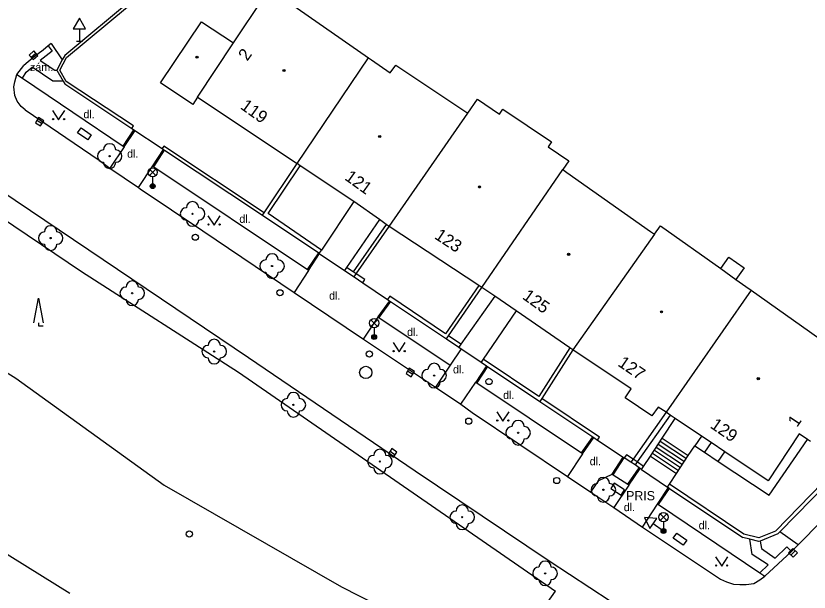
# Model space of a CAD drawing. Extents: x -598341 to -594502, y -1162301 to -1161406.
# Drawn here: x -594705.4 to -594641, y -1161528.7 to -1161481.9 of the extents above; entities that cross this region are included whole.
import ezdxf

# ---------------------------------------------------------------- set-up
doc = ezdxf.new("R2010")
doc.units = 0
for name, color, linetype in [('Vrstva 10', 7, 'Continuous'), ('Vrstva 11', 7, 'Continuous'), ('Vrstva 22', 7, 'Continuous'), ('Vrstva 24', 7, 'Continuous'), ('Vrstva 27', 7, 'Continuous'), ('Vrstva 28', 7, 'Continuous'), ('Vrstva 33', 7, 'Continuous'), ('Vrstva 34', 7, 'Continuous'), ('Vrstva 36', 7, 'Continuous'), ('Vrstva 39', 7, 'Continuous'), ('Vrstva 40', 7, 'Continuous'), ('Vrstva 41', 7, 'Continuous'), ('Vrstva 46', 7, 'Continuous'), ('Vrstva 5', 7, 'Continuous'), ('Vrstva 7', 7, 'Continuous'), ('Vrstva 8', 7, 'Continuous')]:
    doc.layers.add(name, color=color, linetype=linetype)

msp = doc.modelspace()

# ---------------------------------------------------------------- linework, layer by layer
at = {"layer": 'Vrstva 10'}
for p, q in [((-594697.8, -1161494.27), (-594695.46, -1161495.84)), ((-594695.46, -1161495.84), (-594695.32, -1161495.94)), ((-594682.83, -1161504.36), (-594677.19, -1161508.15)), ((-594677.19, -1161508.15), (-594671.36, -1161512.06)), ((-594671.36, -1161512.06), (-594669.28, -1161513.45)), ((-594654.54, -1161523.42), (-594648.22, -1161527.65)), ((-594644.62, -1161527.42), (-594642.44, -1161525.4))]:
    msp.add_line(p, q, dxfattribs=at)
for points in [[(-594702.81, -1161484.33), (-594703.2, -1161484.68), (-594703.91, -1161485.21), (-594704.78, -1161485.94)], [(-594702.57, -1161484.13), (-594702.81, -1161484.33)], [(-594705.34, -1161486.67), (-594704.78, -1161485.94)], [(-594704.67, -1161489.54), (-594705, -1161489.26), (-594705.32, -1161488.84), (-594705.5, -1161488.38), (-594705.59, -1161487.65), (-594705.52, -1161487.27), (-594705.34, -1161486.67)], [(-594650.57, -1161533.78), (-594662.12, -1161526.18), (-594673, -1161518.87), (-594686.54, -1161509.68), (-594707.84, -1161495.33), (-594707.84, -1161495.33), (-594713.27, -1161491.63), (-594717.48, -1161488.75), (-594718.49, -1161487.74)], [(-594704.67, -1161489.54), (-594698.66, -1161493.63), (-594697.8, -1161494.27)], [(-594695.32, -1161495.94), (-594690.24, -1161499.37), (-594682.83, -1161504.36)], [(-594641.89, -1161524.86), (-594628.51, -1161511.28)], [(-594669.28, -1161513.45), (-594668.37, -1161514.12), (-594660.62, -1161519.32)], [(-594660.62, -1161519.32), (-594658.74, -1161520.6)], [(-594658.74, -1161520.6), (-594656.87, -1161521.82)], [(-594656.87, -1161521.82), (-594654.54, -1161523.42)], [(-594642.44, -1161525.4), (-594641.89, -1161524.86)], [(-594648.22, -1161527.65), (-594647.72, -1161527.88), (-594647.16, -1161528.07), (-594646.65, -1161528.1), (-594646.11, -1161528.09), (-594645.51, -1161528), (-594645.02, -1161527.72), (-594644.62, -1161527.42)]]:
    msp.add_lwpolyline(points, dxfattribs=at)
at = {"layer": 'Vrstva 11'}
for p, q in [((-594702.57, -1161484.13), (-594701.66, -1161485.48)), ((-594705.34, -1161486.67), (-594704.89, -1161486.97)), ((-594696.71, -1161492.48), (-594695.84, -1161491.15)), ((-594696.63, -1161492.54), (-594695.75, -1161491.21)), ((-594694.3, -1161494.09), (-594693.44, -1161492.75)), ((-594677.97, -1161496.99), (-594680.62, -1161500.94)), ((-594675.91, -1161498.45), (-594678.58, -1161502.35)), ((-594681.74, -1161502.51), (-594680.83, -1161501.16)), ((-594681.66, -1161502.57), (-594680.76, -1161501.21)), ((-594666.54, -1161504.68), (-594669.29, -1161508.57)), ((-594675.08, -1161505.04), (-594676.04, -1161506.35)), ((-594675, -1161505.09), (-594675.96, -1161506.41)), ((-594664.8, -1161505.87), (-594667.48, -1161509.78)), ((-594676.04, -1161506.35), (-594676, -1161506.38)), ((-594669.27, -1161508.94), (-594670.17, -1161510.28)), ((-594667.2, -1161510.33), (-594668.08, -1161511.65)), ((-594667.12, -1161510.39), (-594668, -1161511.71)), ((-594652.3, -1161514.32), (-594654.98, -1161518.13)), ((-594652.95, -1161516.21), (-594651.88, -1161514.6)), ((-594659.5, -1161517.4), (-594658.58, -1161516.1)), ((-594659.42, -1161517.46), (-594658.49, -1161516.16)), ((-594653.9, -1161517.65), (-594652.95, -1161516.21)), ((-594653.1, -1161516.45), (-594650.98, -1161517.86)), ((-594652.95, -1161516.21), (-594650.82, -1161517.62)), ((-594649.76, -1161516.03), (-594650.3, -1161516.83)), ((-594648.97, -1161516.56), (-594649.51, -1161517.35)), ((-594644.25, -1161520.83), (-594641.13, -1161516.31)), ((-594653.58, -1161517.17), (-594651.46, -1161518.59)), ((-594653.42, -1161516.93), (-594651.3, -1161518.35)), ((-594653.26, -1161516.69), (-594651.14, -1161518.1)), ((-594650.82, -1161517.62), (-594650.3, -1161516.83)), ((-594650.3, -1161516.83), (-594649.51, -1161517.35)), ((-594657, -1161519.12), (-594656.1, -1161517.75)), ((-594656.92, -1161519.17), (-594656.02, -1161517.8)), ((-594654.46, -1161518.49), (-594653.9, -1161517.65)), ((-594653.9, -1161517.65), (-594651.77, -1161519.07)), ((-594653.74, -1161517.41), (-594651.62, -1161518.83)), ((-594651.77, -1161519.07), (-594650.82, -1161517.62)), ((-594649.51, -1161517.35), (-594648.39, -1161518.1)), ((-594648.39, -1161518.1), (-594647.86, -1161517.3)), ((-594654.98, -1161518.13), (-594655.15, -1161518.38)), ((-594648.39, -1161518.1), (-594644.25, -1161520.83)), ((-594655.73, -1161519.95), (-594654.81, -1161518.62)), ((-594655.65, -1161520.01), (-594654.73, -1161518.67)), ((-594652.34, -1161519.93), (-594651.77, -1161519.07)), ((-594653.33, -1161521.55), (-594652.44, -1161520.22)), ((-594653.25, -1161521.6), (-594652.36, -1161520.28)), ((-594641.89, -1161524.86), (-594643.38, -1161523.8))]:
    msp.add_line(p, q, dxfattribs=at)
for points in [[(-594702.81, -1161484.33), (-594702.48, -1161484.77), (-594703.46, -1161485.53), (-594702.26, -1161486.32), (-594702.1, -1161486.32)], [(-594744.77, -1161484.99), (-594722.47, -1161500.75), (-594705.44, -1161511.34), (-594693.39, -1161520.03), (-594678.98, -1161528.27), (-594666.01, -1161534.88), (-594661.61, -1161528.62)], [(-594704.89, -1161486.97), (-594704.58, -1161486.48), (-594704.1, -1161486.07)], [(-594701.59, -1161487.19), (-594702.41, -1161487.19), (-594704.1, -1161486.07)], [(-594724.47, -1161487.1), (-594714.36, -1161493.06), (-594700.1, -1161502.65), (-594687.35, -1161510.84), (-594661.61, -1161528.62)], [(-594704.89, -1161486.97), (-594696.71, -1161492.48)], [(-594696.63, -1161492.54), (-594697.8, -1161494.27)], [(-594696.71, -1161492.48), (-594696.63, -1161492.54)], [(-594694.22, -1161494.15), (-594693.36, -1161492.8)], [(-594695.46, -1161495.84), (-594694.3, -1161494.09)], [(-594694.3, -1161494.09), (-594694.22, -1161494.15)], [(-594694.22, -1161494.15), (-594681.74, -1161502.51)], [(-594648.19, -1161502.43), (-594647.54, -1161501.51), (-594646.29, -1161502.37), (-594646.96, -1161503.31)], [(-594681.66, -1161502.57), (-594682.83, -1161504.36)], [(-594681.74, -1161502.51), (-594681.66, -1161502.57)], [(-594677.19, -1161508.15), (-594676, -1161506.38)], [(-594676, -1161506.38), (-594675.96, -1161506.41)], [(-594675.96, -1161506.41), (-594670.17, -1161510.28)], [(-594670.17, -1161510.28), (-594671.36, -1161512.06)], [(-594669.28, -1161513.45), (-594668.08, -1161511.65)], [(-594668.08, -1161511.65), (-594668, -1161511.71)], [(-594668, -1161511.71), (-594659.5, -1161517.4)], [(-594659.42, -1161517.46), (-594660.62, -1161519.32)], [(-594659.5, -1161517.4), (-594659.42, -1161517.46)], [(-594658.74, -1161520.6), (-594658.09, -1161519.65), (-594657, -1161519.12)], [(-594657, -1161519.12), (-594656.92, -1161519.17)], [(-594656.92, -1161519.17), (-594655.73, -1161519.95)], [(-594655.65, -1161520.01), (-594656.87, -1161521.82)], [(-594655.73, -1161519.95), (-594655.65, -1161520.01)], [(-594654.54, -1161523.42), (-594653.33, -1161521.55)], [(-594653.33, -1161521.55), (-594653.25, -1161521.6)], [(-594653.25, -1161521.6), (-594645.02, -1161527.13)], [(-594645.02, -1161527.13), (-594644.35, -1161526.5), (-594645.63, -1161525.64), (-594645.83, -1161524.41)], [(-594644.99, -1161524.56), (-594644.87, -1161525.17), (-594643.76, -1161525.94), (-594642.83, -1161525.04), (-594642.44, -1161525.4)], [(-594645.02, -1161527.13), (-594644.62, -1161527.42)]]:
    msp.add_lwpolyline(points, dxfattribs=at)
at = {"layer": 'Vrstva 22'}
for centre in [(-594697.81, -1161493.29), (-594691.08, -1161497.98), (-594702.6, -1161499.95), (-594684.62, -1161502.22), (-594695.98, -1161504.43), (-594689.32, -1161509.17), (-594671.46, -1161511.12), (-594682.89, -1161513.49), (-594664.64, -1161515.76), (-594675.87, -1161518.1), (-594657.72, -1161520.39), (-594669.18, -1161522.62), (-594662.45, -1161527.18)]:
    msp.add_circle(centre, 0.05, dxfattribs=at)
for centre, start, end in [((-594697.81, -1161492.79), 0, 180), ((-594698.31, -1161493.29), 90, 270), ((-594697.31, -1161493.29), 270, 90), ((-594697.81, -1161493.79), 180, 0), ((-594691.08, -1161497.48), 0, 180), ((-594691.58, -1161497.98), 90, 270), ((-594690.58, -1161497.98), 270, 90), ((-594691.08, -1161498.48), 180, 0), ((-594702.6, -1161499.45), 0, 180), ((-594703.1, -1161499.95), 90, 270), ((-594702.1, -1161499.95), 270, 90), ((-594702.6, -1161500.45), 180, 0), ((-594685.12, -1161502.22), 90, 270), ((-594684.62, -1161501.72), 0, 180), ((-594684.12, -1161502.22), 270, 90), ((-594684.62, -1161502.72), 180, 0), ((-594695.98, -1161503.93), 0, 180), ((-594696.48, -1161504.43), 90, 270), ((-594695.48, -1161504.43), 270, 90), ((-594695.98, -1161504.93), 180, 0), ((-594689.32, -1161508.67), 0, 180), ((-594689.82, -1161509.17), 90, 270), ((-594688.82, -1161509.17), 270, 90), ((-594689.32, -1161509.67), 180, 0), ((-594671.46, -1161510.62), 0, 180), ((-594671.96, -1161511.12), 90, 270), ((-594670.96, -1161511.12), 270, 90), ((-594671.46, -1161511.62), 180, 0), ((-594682.89, -1161512.99), 0, 180), ((-594683.39, -1161513.49), 90, 270), ((-594682.39, -1161513.49), 270, 90), ((-594682.89, -1161513.99), 180, 0), ((-594665.14, -1161515.76), 90, 270), ((-594664.64, -1161515.26), 0, 180), ((-594664.14, -1161515.76), 270, 90), ((-594664.64, -1161516.26), 180, 0), ((-594675.87, -1161517.6), 0, 180), ((-594676.37, -1161518.1), 90, 270), ((-594675.37, -1161518.1), 270, 90), ((-594675.87, -1161518.6), 180, 0), ((-594657.72, -1161519.89), 0, 180), ((-594658.22, -1161520.39), 90, 270), ((-594657.22, -1161520.39), 270, 90), ((-594657.72, -1161520.89), 180, 0), ((-594669.18, -1161522.12), 0, 180), ((-594669.68, -1161522.62), 90, 270), ((-594668.68, -1161522.62), 270, 90), ((-594669.18, -1161523.12), 180, 0), ((-594662.45, -1161526.68), 0, 180), ((-594662.95, -1161527.18), 90, 270), ((-594661.95, -1161527.18), 270, 90), ((-594662.45, -1161527.68), 180, 0)]:
    msp.add_arc(centre, 0.5, start, end, dxfattribs=at)
at = {"layer": 'Vrstva 24'}
for points in [[(-594700.41, -1161491.4), (-594700.12, -1161490.99), (-594699.3, -1161491.57), (-594699.59, -1161491.98), (-594700.41, -1161491.4)], [(-594652.04, -1161524.32), (-594651.75, -1161523.91), (-594650.94, -1161524.49), (-594651.23, -1161524.9), (-594652.04, -1161524.32)]]:
    msp.add_lwpolyline(points, dxfattribs=at)
msp.add_lwpolyline([(-594657.125, -1161520.28), (-594656.285, -1161520.821), (-594656.014, -1161520.401), (-594656.855, -1161519.86)], close=True, dxfattribs=at)
at = {"layer": 'Vrstva 27'}
for p, q in [((-594704.187, -1161485.266), (-594703.813, -1161484.934)), ((-594703.714, -1161490.371), (-594703.286, -1161490.63)), ((-594673.612, -1161510.738), (-594673.188, -1161511.003)), ((-594675.037, -1161517.26), (-594674.624, -1161517.541)), ((-594642.493, -1161525.7), (-594642.147, -1161525.339))]:
    msp.add_line(p, q, dxfattribs=at)
for points in [[(-594704.021, -1161485.453), (-594703.647, -1161485.121), (-594703.979, -1161484.747), (-594704.353, -1161485.079)], [(-594703.844, -1161490.585), (-594703.416, -1161490.844), (-594703.157, -1161490.416), (-594703.585, -1161490.157)], [(-594673.745, -1161510.95), (-594673.321, -1161511.215), (-594673.055, -1161510.791), (-594673.479, -1161510.526)], [(-594675.178, -1161517.466), (-594674.764, -1161517.748), (-594674.483, -1161517.334), (-594674.896, -1161517.053)], [(-594642.312, -1161525.873), (-594641.967, -1161525.512), (-594642.328, -1161525.166), (-594642.674, -1161525.527)]]:
    msp.add_lwpolyline(points, close=True, dxfattribs=at)
msp.add_circle((-594677.01, -1161510.86), 0.5, dxfattribs=at)
at = {"layer": 'Vrstva 28'}
for centre in [(-594690.85, -1161499.88), (-594683.98, -1161504.39), (-594676.72, -1161509.36), (-594667.01, -1161511.6), (-594668.65, -1161514.82), (-594661.5, -1161519.64), (-594691.34, -1161523.99)]:
    msp.add_circle(centre, 0.25, dxfattribs=at)
at = {"layer": 'Vrstva 33'}
for p, q in [((-594694.585, -1161494.87), (-594694.055, -1161494.34)), ((-594694.585, -1161494.34), (-594694.055, -1161494.87)), ((-594694.32, -1161494.98), (-594694.32, -1161495.73)), ((-594676.595, -1161507.12), (-594676.065, -1161506.59)), ((-594676.595, -1161506.59), (-594676.065, -1161507.12)), ((-594676.33, -1161507.23), (-594676.33, -1161507.98)), ((-594653.105, -1161522.88), (-594652.575, -1161522.35)), ((-594653.105, -1161522.35), (-594652.575, -1161522.88)), ((-594652.84, -1161522.99), (-594652.84, -1161523.74))]:
    msp.add_line(p, q, dxfattribs=at)
for centre, radius in [((-594694.32, -1161494.605), 0.375), ((-594694.32, -1161495.73), 0.2), ((-594694.32, -1161495.73), 0.145), ((-594694.32, -1161495.73), 0.0876), ((-594676.33, -1161506.855), 0.375), ((-594676.33, -1161507.98), 0.2), ((-594676.33, -1161507.98), 0.145), ((-594676.33, -1161507.98), 0.0876), ((-594652.84, -1161522.615), 0.375), ((-594652.84, -1161523.74), 0.2), ((-594652.84, -1161523.74), 0.145), ((-594652.84, -1161523.74), 0.0876)]:
    msp.add_circle(centre, radius, dxfattribs=at)
at = {"layer": 'Vrstva 34'}
for p, q in [((-594700.26, -1161482.942), (-594700.26, -1161483.96)), ((-594700.51, -1161483.96), (-594700.01, -1161483.96)), ((-594653.666, -1161523.145), (-594652.84, -1161523.74))]:
    msp.add_line(p, q, dxfattribs=at)
for points in [[(-594700.76, -1161482.942), (-594699.76, -1161482.942), (-594700.26, -1161482.076)], [(-594653.958, -1161523.551), (-594653.374, -1161522.739), (-594654.369, -1161522.639)]]:
    msp.add_lwpolyline(points, close=True, dxfattribs=at)
at = {"layer": 'Vrstva 36'}
for points in [[(-594702.45, -1161489.58), (-594701.95, -1161490.33), (-594701.45, -1161489.58)], [(-594689.83, -1161498.15), (-594689.33, -1161498.9), (-594688.83, -1161498.15)], [(-594703.965, -1161506.83), (-594703.59, -1161504.83), (-594703.215, -1161506.83)], [(-594703.59, -1161506.83), (-594703.59, -1161507.08), (-594703.215, -1161507.08)], [(-594674.8, -1161508.43), (-594674.3, -1161509.18), (-594673.8, -1161508.43)], [(-594666.38, -1161514.07), (-594665.88, -1161514.82), (-594665.38, -1161514.07)], [(-594648.61, -1161525.84), (-594648.11, -1161526.59), (-594647.61, -1161525.84)]]:
    msp.add_lwpolyline(points, dxfattribs=at)
for centre in [(-594702.4, -1161490.28), (-594701.501, -1161490.28), (-594689.78, -1161498.85), (-594688.881, -1161498.85), (-594674.75, -1161509.13), (-594673.851, -1161509.13), (-594666.33, -1161514.77), (-594665.431, -1161514.77), (-594648.56, -1161526.54), (-594647.661, -1161526.54)]:
    msp.add_circle(centre, 0.05, dxfattribs=at)
at = {"layer": 'Vrstva 39'}
for centre, radius in [((-594690.71, -1161485.25), 0.09), ((-594690.71, -1161485.25), 0.0398), ((-594683.66, -1161486.34), 0.09), ((-594683.66, -1161486.34), 0.0398), ((-594675.88, -1161491.7), 0.09), ((-594675.88, -1161491.7), 0.0398), ((-594667.78, -1161495.79), 0.09), ((-594667.78, -1161495.79), 0.0398), ((-594660.54, -1161501.26), 0.09), ((-594660.54, -1161501.26), 0.0398), ((-594653, -1161505.94), 0.09), ((-594653, -1161505.94), 0.0398), ((-594645.14, -1161511.36), 0.09), ((-594645.14, -1161511.36), 0.0398)]:
    msp.add_circle(centre, radius, dxfattribs=at)
at = {"layer": 'Vrstva 5'}
for p, q in [((-594687.74, -1161484.1), (-594684.82, -1161479.7)), ((-594684.82, -1161479.7), (-594676.78, -1161485.31)), ((-594693.69, -1161487.35), (-594690.34, -1161482.38)), ((-594690.34, -1161482.38), (-594687.74, -1161484.1)), ((-594690.67, -1161488.5), (-594687.74, -1161484.1)), ((-594682.58, -1161493.9), (-594676.78, -1161485.31)), ((-594676.78, -1161485.31), (-594676.54, -1161485.48)), ((-594676.54, -1161485.48), (-594675.04, -1161486.52)), ((-594675.04, -1161486.52), (-594674.57, -1161485.9)), ((-594674.57, -1161485.9), (-594668.97, -1161489.64)), ((-594691.06, -1161489.09), (-594693.69, -1161487.35)), ((-594690.67, -1161488.5), (-594691.06, -1161489.09)), ((-594690.67, -1161488.5), (-594682.58, -1161493.9)), ((-594668.72, -1161489.8), (-594667.93, -1161488.66)), ((-594667.93, -1161488.66), (-594666.15, -1161489.87)), ((-594666.15, -1161489.87), (-594665.88, -1161489.48)), ((-594665.88, -1161489.48), (-594661.93, -1161492.14)), ((-594675.11, -1161499.01), (-594668.72, -1161489.8)), ((-594668.97, -1161489.64), (-594668.72, -1161489.8)), ((-594661.93, -1161492.14), (-594662.2, -1161492.54)), ((-594662.2, -1161492.54), (-594660.53, -1161493.68)), ((-594682.33, -1161494.07), (-594682.58, -1161493.9)), ((-594660.53, -1161493.68), (-594661.02, -1161494.39)), ((-594677.97, -1161496.99), (-594682.33, -1161494.07)), ((-594667.59, -1161503.95), (-594661.02, -1161494.39)), ((-594661.02, -1161494.39), (-594660.69, -1161494.62)), ((-594660.69, -1161494.62), (-594653.89, -1161499.41)), ((-594675.91, -1161498.45), (-594677.97, -1161496.99)), ((-594675.36, -1161498.84), (-594675.91, -1161498.45)), ((-594675.11, -1161499.01), (-594675.36, -1161498.84)), ((-594667.84, -1161503.79), (-594675.11, -1161499.01)), ((-594653.56, -1161499.64), (-594653.08, -1161498.96)), ((-594653.08, -1161498.96), (-594648.19, -1161502.43)), ((-594653.56, -1161499.64), (-594660.2, -1161509.03)), ((-594653.89, -1161499.41), (-594653.56, -1161499.64)), ((-594648.19, -1161502.43), (-594646.96, -1161503.31)), ((-594646.96, -1161503.31), (-594646.14, -1161503.89)), ((-594667.59, -1161503.95), (-594667.84, -1161503.79)), ((-594666.54, -1161504.68), (-594667.59, -1161503.95)), ((-594645.73, -1161504.18), (-594652.63, -1161514.1)), ((-594646.14, -1161503.89), (-594645.73, -1161504.18)), ((-594645.73, -1161504.18), (-594637.77, -1161509.83)), ((-594664.8, -1161505.87), (-594666.54, -1161504.68)), ((-594660.45, -1161508.86), (-594664.8, -1161505.87)), ((-594660.2, -1161509.03), (-594660.45, -1161508.86)), ((-594655.47, -1161512.2), (-594660.2, -1161509.03)), ((-594655.96, -1161512.92), (-594655.47, -1161512.2)), ((-594653.77, -1161514.39), (-594655.96, -1161512.92)), ((-594653.28, -1161513.67), (-594653.77, -1161514.39)), ((-594652.63, -1161514.1), (-594653.28, -1161513.67)), ((-594652.3, -1161514.32), (-594652.63, -1161514.1)), ((-594651.88, -1161514.6), (-594652.3, -1161514.32)), ((-594649.76, -1161516.03), (-594651.88, -1161514.6)), ((-594641.81, -1161515.86), (-594644.35, -1161519.66)), ((-594641.13, -1161516.31), (-594641.81, -1161515.86)), ((-594648.97, -1161516.56), (-594649.76, -1161516.03)), ((-594647.86, -1161517.3), (-594648.97, -1161516.56)), ((-594640.89, -1161516.47), (-594641.13, -1161516.31)), ((-594644.35, -1161519.66), (-594647.86, -1161517.3)), ((-594716.31, -1161519.3), (-594701.04, -1161528.8))]:
    msp.add_line(p, q, dxfattribs=at)
at = {"layer": 'Vrstva 7'}
for p, q in [((-594688.08, -1161473.97), (-594701.46, -1161485.11)), ((-594701.46, -1161487.42), (-594696, -1161491.04)), ((-594693.54, -1161492.68), (-594693.44, -1161492.75)), ((-594693.44, -1161492.75), (-594693.36, -1161492.8)), ((-594693.36, -1161492.8), (-594685.4, -1161498.08)), ((-594685.27, -1161497.89), (-594682.58, -1161493.9)), ((-594685.4, -1161498.08), (-594685.27, -1161497.89)), ((-594685.4, -1161498.08), (-594680.83, -1161501.16)), ((-594675.36, -1161498.84), (-594678.04, -1161502.69)), ((-594677.78, -1161502.85), (-594675.11, -1161499.01)), ((-594680.79, -1161501.19), (-594680.62, -1161500.94)), ((-594680.83, -1161501.16), (-594680.79, -1161501.19)), ((-594678.58, -1161502.35), (-594678.73, -1161502.57)), ((-594678.04, -1161502.69), (-594678.58, -1161502.35)), ((-594678.73, -1161502.57), (-594677.95, -1161503.1)), ((-594677.95, -1161503.1), (-594677.78, -1161502.85)), ((-594677.95, -1161503.1), (-594677.25, -1161503.57)), ((-594670.3, -1161507.89), (-594667.59, -1161503.95)), ((-594675.24, -1161504.93), (-594675.08, -1161505.04)), ((-594675.08, -1161505.04), (-594675, -1161505.09)), ((-594675, -1161505.09), (-594670.47, -1161508.14)), ((-594670.47, -1161508.14), (-594670.3, -1161507.89)), ((-594670.47, -1161508.14), (-594669.46, -1161508.81)), ((-594669.29, -1161508.57), (-594670.3, -1161507.89)), ((-594669.29, -1161508.57), (-594669.46, -1161508.81)), ((-594660.45, -1161508.86), (-594662.97, -1161512.81)), ((-594660.2, -1161509.03), (-594662.72, -1161512.98)), ((-594667.48, -1161509.78), (-594667.65, -1161510.03)), ((-594667.65, -1161510.03), (-594667.2, -1161510.33)), ((-594662.97, -1161512.81), (-594667.48, -1161509.78)), ((-594667.2, -1161510.33), (-594667.12, -1161510.39)), ((-594667.12, -1161510.39), (-594662.88, -1161513.23)), ((-594662.72, -1161512.98), (-594662.88, -1161513.23)), ((-594662.88, -1161513.23), (-594658.58, -1161516.1)), ((-594632.62, -1161512.75), (-594643.38, -1161523.8)), ((-594652.63, -1161514.1), (-594655.31, -1161517.91)), ((-594658.58, -1161516.1), (-594658.49, -1161516.16)), ((-594658.49, -1161516.16), (-594658.19, -1161516.36)), ((-594655.48, -1161518.16), (-594656.02, -1161517.8)), ((-594655.31, -1161517.91), (-594655.48, -1161518.16)), ((-594655.15, -1161518.38), (-594655.48, -1161518.16)), ((-594654.81, -1161518.62), (-594655.15, -1161518.38)), ((-594654.73, -1161518.67), (-594654.81, -1161518.62)), ((-594654.63, -1161518.74), (-594654.73, -1161518.67)), ((-594652.51, -1161520.18), (-594652.34, -1161519.93)), ((-594652.51, -1161520.18), (-594652.44, -1161520.22)), ((-594652.44, -1161520.22), (-594652.36, -1161520.28)), ((-594652.36, -1161520.28), (-594646.4, -1161524.27)), ((-594645.83, -1161524.41), (-594646.4, -1161524.27)), ((-594643.54, -1161523.96), (-594644.99, -1161524.56)), ((-594643.38, -1161523.8), (-594643.54, -1161523.96)), ((-594645.09, -1161524.6), (-594645.83, -1161524.41)), ((-594644.99, -1161524.56), (-594645.09, -1161524.6))]:
    msp.add_line(p, q, dxfattribs=at)
for points in [[(-594696, -1161491.04), (-594695.86, -1161490.83), (-594701.33, -1161487.23), (-594701.85, -1161486.32), (-594701.31, -1161485.29), (-594682.94, -1161469.98)], [(-594701.66, -1161485.48), (-594702.1, -1161486.32)], [(-594701.46, -1161485.11), (-594701.66, -1161485.48)], [(-594702.1, -1161486.32), (-594701.59, -1161487.19)], [(-594701.59, -1161487.19), (-594701.46, -1161487.42)], [(-594685.27, -1161497.89), (-594693.41, -1161492.48), (-594693.54, -1161492.68)], [(-594680.62, -1161500.94), (-594684.95, -1161497.95), (-594682.33, -1161494.07)], [(-594677.78, -1161502.85), (-594678.04, -1161502.69)], [(-594677.25, -1161503.57), (-594677.08, -1161503.32), (-594677.78, -1161502.85)], [(-594667.84, -1161503.79), (-594670.55, -1161507.72), (-594675.07, -1161504.68), (-594675.24, -1161504.93)], [(-594658.19, -1161516.36), (-594658.02, -1161516.11), (-594662.72, -1161512.98)], [(-594655.31, -1161517.91), (-594655.85, -1161517.55), (-594656.02, -1161517.8)], [(-594638.02, -1161517.87), (-594643.75, -1161523.75), (-594645.1, -1161524.3), (-594646.3, -1161523.99), (-594652.34, -1161519.93)], [(-594654.98, -1161518.13), (-594655.31, -1161517.91)], [(-594654.46, -1161518.49), (-594654.98, -1161518.13)], [(-594654.63, -1161518.74), (-594654.46, -1161518.49)]]:
    msp.add_lwpolyline(points, dxfattribs=at)
at = {"layer": 'Vrstva 8'}
for p, q in [((-594696, -1161491.04), (-594693.54, -1161492.68)), ((-594680.79, -1161501.19), (-594678.73, -1161502.57)), ((-594677.25, -1161503.57), (-594675.24, -1161504.93)), ((-594669.46, -1161508.81), (-594667.65, -1161510.03)), ((-594658.19, -1161516.36), (-594656.02, -1161517.8)), ((-594654.63, -1161518.74), (-594652.51, -1161520.18))]:
    msp.add_line(p, q, dxfattribs=at)

# ---------------------------------------------------------------- texts
at = {"layer": 'Vrstva 40'}
for s, p in [('zám.', (-594704.28, -1161486.39)), ('dl.', (-594699.94, -1161490.21)), ('dl.', (-594696.39, -1161493.42)), ('dl.', (-594687.28, -1161498.71)), ('dl.', (-594679.99, -1161504.95)), ('dl.', (-594673.66, -1161507.9)), ('dl.', (-594669.93, -1161510.94)), ('dl.', (-594665.86, -1161513.02)), ('dl.', (-594658.83, -1161518.4)), ('dl.', (-594656.06, -1161522.13)), ('dl.', (-594649.98, -1161523.6))]:
    msp.add_text(s, height=0.65, dxfattribs=at).set_placement(p)
at = {"layer": 'Vrstva 41'}
msp.add_text('PRIS', height=0.75, dxfattribs=at).set_placement((-594655.87, -1161521.25))
at = {"layer": 'Vrstva 46'}
for s, rotation, p in [('2', 55.16, (-594686.63, -1161485.62)), ('119', 324.35, (-594687.26, -1161489.39)), ('121', 324.35, (-594678.79, -1161495.16)), ('123', 326.62, (-594671.5, -1161499.94)), ('125', 324.32, (-594664.36, -1161504.83)), ('127', 325.7, (-594656.61, -1161510.28)), ('1', 56.02, (-594641.99, -1161515.37)), ('129', 325.42, (-594649.11, -1161515.31))]:
    msp.add_text(s, height=1, rotation=rotation, dxfattribs=at).set_placement(p)

doc.saveas('drawing.dxf')
